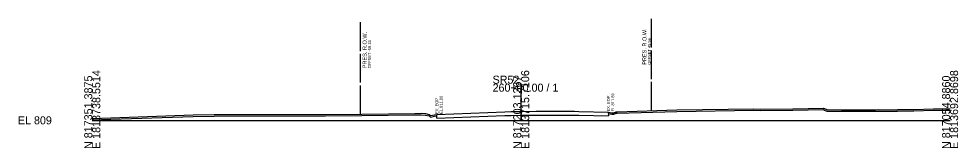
# Model space of a CAD drawing. Extents: x -50 to 1838305, y -27 to 820775.
# Drawn here: x 2974.3 to 3302.8, y 1490.3 to 1535.4 of the extents above; entities that cross this region are included whole.
import ezdxf

# ---------------------------------------------------------------- set-up
doc = ezdxf.new("R2010")
doc.units = 0
for name, color, linetype in [('DESIGN - SHEET - Light Grid', 7, 'Continuous'), ('SURVEY - GROUND - Bottom of Topsoil Layer', 7, 'Continuous'), ('SURVEY - GROUND - Existing Pavement Layer', 7, 'Continuous'), ('SURVEY - GROUND - Existing Pavement Text', 7, 'Continuous'), ('SURVEY - GROUND - Top of Ground', 7, 'Continuous'), ('SURVEY - PROPERTY - ROW Lines', 7, 'Continuous'), ('SURVEY - PROPERTY - ROW Lines Text', 7, 'Continuous')]:
    doc.layers.add(name, color=color, linetype=linetype)

msp = doc.modelspace()

# ---------------------------------------------------------------- linework, layer by layer
at = {"layer": 'DESIGN - SHEET - Light Grid'}
for p, q in [((3150, 1500), (3150, 1512.78)), ((3000, 1500), (3150, 1500)), ((3150, 1500), (3300, 1500))]:
    msp.add_line(p, q, dxfattribs=at)
at = {"layer": 'SURVEY - GROUND - Bottom of Topsoil Layer'}
for p, q in [((3035.25, 1501.37), (3042.58, 1501.48)), ((3042.58, 1501.48), (3081.48, 1501.58)), ((3081.48, 1501.58), (3094.27, 1501.67)), ((3094.27, 1501.67), (3112.81, 1501.91)), ((3112.81, 1501.91), (3115.08, 1501.97)), ((3115.08, 1501.97), (3116.57, 1501.83)), ((3116.57, 1501.83), (3117.81, 1501.56)), ((3117.81, 1501.56), (3118.32, 1501.13)), ((3118.32, 1501.13), (3119.74, 1501.41)), ((3119.74, 1501.41), (3120.52, 1501.56)), ((3120.52, 1501.56), (3120.52, 1502.06)), ((3180.52, 1502.39), (3180.52, 1502.89)), ((3180.52, 1502.39), (3181.71, 1502.15)), ((3181.71, 1502.15), (3182.43, 1502.13)), ((3182.43, 1502.13), (3183.17, 1502.48)), ((3183.17, 1502.48), (3183.53, 1502.5)), ((3183.53, 1502.5), (3204.39, 1503.13)), ((3204.39, 1503.13), (3231.36, 1503.49)), ((3231.36, 1503.49), (3233.78, 1503.37)), ((3233.78, 1503.37), (3245.05, 1503.54)), ((3245.05, 1503.54), (3255.69, 1503.76)), ((3255.69, 1503.76), (3256.11, 1503.6)), ((3256.11, 1503.6), (3256.92, 1503.22)), ((3256.92, 1503.22), (3262.01, 1503.2)), ((3262.01, 1503.2), (3262.59, 1503.21)), ((3262.59, 1503.21), (3270.19, 1503.21)), ((3270.19, 1503.21), (3273.9, 1503.19)), ((3273.9, 1503.19), (3274.79, 1503.22)), ((3274.79, 1503.22), (3281.19, 1503.19)), ((3281.19, 1503.19), (3281.66, 1503.23)), ((3281.66, 1503.23), (3287.36, 1503.26)), ((3287.36, 1503.26), (3294.23, 1503.53)), ((3294.23, 1503.53), (3300, 1503.57)), ((3000, 1500.18), (3006.54, 1500.37)), ((3006.54, 1500.37), (3035.25, 1501.37))]:
    msp.add_line(p, q, dxfattribs=at)
at = {"layer": 'SURVEY - GROUND - Existing Pavement Layer'}
for p, q in [((3120.52, 1500.72), (3120.52, 1502.06)), ((3120.52, 1500.72), (3144.24, 1501.68)), ((3144.24, 1501.68), (3146.46, 1501.7)), ((3146.46, 1501.7), (3150, 1501.76)), ((3150, 1501.76), (3150.44, 1501.77)), ((3150.44, 1501.77), (3155.28, 1501.82)), ((3155.28, 1501.82), (3156.34, 1501.83)), ((3156.34, 1501.83), (3168.7, 1501.82)), ((3168.7, 1501.82), (3170.2, 1501.77)), ((3170.2, 1501.77), (3180.52, 1501.55)), ((3180.52, 1502.89), (3180.52, 1501.55))]:
    msp.add_line(p, q, dxfattribs=at)
at = {"layer": 'SURVEY - GROUND - Top of Ground'}
msp.add_lwpolyline([(3000, 1500.68), (3006.54, 1500.87), (3035.25, 1501.87), (3042.58, 1501.98), (3081.48, 1502.08), (3094.27, 1502.17), (3112.81, 1502.41), (3115.08, 1502.47), (3116.57, 1502.33), (3117.81, 1502.06), (3118.32, 1501.63), (3119.74, 1501.91), (3120.52, 1502.06), (3144.24, 1503.02), (3146.46, 1503.04), (3150, 1503.1), (3150.44, 1503.11), (3155.28, 1503.16), (3156.34, 1503.17), (3168.7, 1503.16), (3170.2, 1503.11), (3180.52, 1502.89), (3181.71, 1502.65), (3182.43, 1502.63), (3183.17, 1502.98), (3183.53, 1503), (3204.39, 1503.63), (3231.36, 1503.99), (3233.78, 1503.87), (3245.05, 1504.04), (3255.69, 1504.26), (3256.11, 1504.1), (3256.92, 1503.72), (3262.01, 1503.7), (3262.59, 1503.71), (3270.19, 1503.71), (3273.9, 1503.69), (3274.79, 1503.72), (3281.19, 1503.69), (3281.66, 1503.73), (3287.36, 1503.76), (3294.23, 1504.03), (3300, 1504.07)], dxfattribs=at)
at = {"layer": 'SURVEY - PROPERTY - ROW Lines'}
for p, q in [((3195.56, 1525.37), (3195.56, 1535.37)), ((3093.82, 1524.16), (3093.82, 1534.16)), ((3093.82, 1513.16), (3093.82, 1523.16)), ((3195.56, 1514.37), (3195.56, 1524.37)), ((3093.82, 1502.16), (3093.82, 1512.16)), ((3195.56, 1503.37), (3195.56, 1513.37))]:
    msp.add_line(p, q, dxfattribs=at)

# ---------------------------------------------------------------- texts
at = {"layer": 'DESIGN - SHEET - Light Grid'}
for s, p in [('N 817351.3875', (3000, 1490)), ('E 1813738.5514', (3002.8, 1490)), ('N 817203.1367', (3150, 1490)), ('E 1813715.7106', (3152.8, 1490)), ('N 817054.8860', (3300, 1490)), ('E 1813692.8698', (3302.8, 1490))]:
    msp.add_text(s, height=2.8, rotation=90, dxfattribs=at).set_placement(p)
for s, p in [('SR52', (3140, 1512.78)), ('260+00.00 / 1', (3140, 1509.98)), ('EL 809', (2974, 1498.6))]:
    msp.add_text(s, height=2.8, dxfattribs=at).set_placement(p)
at = {"layer": 'SURVEY - GROUND - Existing Pavement Text'}
for s, p in [('EL.811.06', (3122.52, 1502.26)), ('EX. EOP', (3181.02, 1503.09)), ('EL.811.89', (3182.52, 1503.09)), ('EX. EOP', (3121.02, 1502.26))]:
    msp.add_text(s, height=1, rotation=90, dxfattribs=at).set_placement(p)
at = {"layer": 'SURVEY - PROPERTY - ROW Lines Text'}
for s, height, p in [('PRES. R.O.W.', 1.4, (3193.81, 1519.37)), ('PRES. R.O.W.', 1.4, (3095.97, 1518.16)), ('OFFSET 45.56', 1, (3195.31, 1519.37)), ('OFFSET -56.18', 1, (3097.47, 1518.16))]:
    msp.add_text(s, height=height, rotation=90, dxfattribs=at).set_placement(p)

doc.saveas('drawing.dxf')
